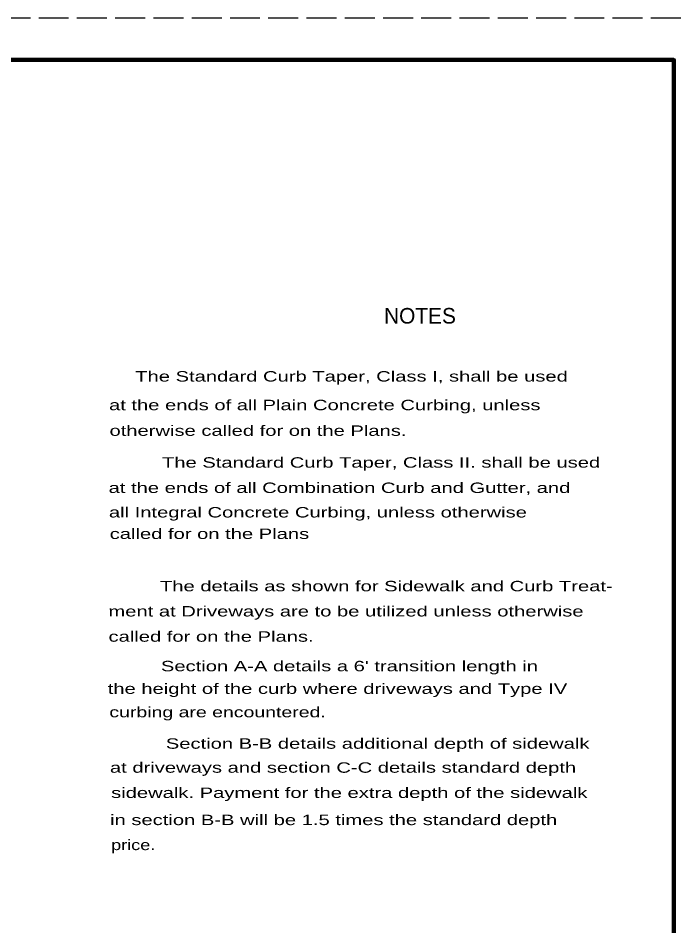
# Model space of a CAD drawing. Extents: x 75.6 to 110.9, y 28 to 50.
# Drawn here: x 102.83 to 110.8, y 39.07 to 49.98 of the extents above; entities that cross this region are included whole.
import ezdxf

# ---------------------------------------------------------------- set-up
doc = ezdxf.new("R2010")
doc.units = 0
doc.header["$LTSCALE"] = 0.06
doc.header["$PDMODE"] = 32
doc.header["$PDSIZE"] = 0.03
doc.linetypes.add('LONG_DASHED', pattern=[7.5, 6, -1.5])
doc.layers.add('1', color=7, linetype='Continuous', lineweight=25)
doc.layers.add('3', color=7, linetype='Continuous', lineweight=13)

msp = doc.modelspace()

# ---------------------------------------------------------------- linework, layer by layer
at = {"layer": '1', "linetype": 'LONG_DASHED'}
msp.add_line((110.8, 49.97992), (75.6, 49.97992), dxfattribs=at)
at = {"layer": '1', "lineweight": 158}
msp.add_line((110.71667, 49.47992), (78.21667, 49.47992), dxfattribs=at)
msp.add_lwpolyline([(110.71667, 49.47992), (110.71667, 28.47992), (78.21667, 28.47992)], dxfattribs=at)
at = {"layer": '1'}
msp.add_point((110.71667, 49.47992), dxfattribs=at)

# ---------------------------------------------------------------- texts
for s, width, p in [('The Standard Curb Taper, Class II. shall be used', 1.45, (104.56267, 44.57692)), ('at the ends of all Combination Curb and Gutter, and', 1.45, (103.92058, 44.27275)), ('all Integral Concrete Curbing, unless otherwise ', 1.45, (103.92417, 43.97825)), ('called for on the Plans', 1.45, (103.93383, 43.71992)), ('The details as shown for Sidewalk and Curb Treat-', 1.45, (104.53833, 43.09083)), ('ment at Driveways are to be utilized unless otherwise', 1.45, (103.91858, 42.78833)), ('called for on the Plans. ', 1.45, (103.91975, 42.48475)), ("Section A-A details a 6' transition length in", 1.45, (104.5495, 42.1295)), ('the height of the curb where driveways and Type IV', 1.45, (103.91025, 41.85792)), ('curbing are encountered.', 1.4, (103.92958, 41.57667)), ('Section B-B details additional depth of sidewalk', 1.45, (104.60858, 41.1985)), ('at driveways and section C-C details standard depth', 1.45, (103.93675, 40.91008)), ('sidewalk. Payment for the extra depth of the sidewalk', 1.45, (103.95092, 40.60692)), ('in section B-B will be 1.5 times the standard depth', 1.45, (103.93858, 40.28067)), ('price.', 1.3, (103.95083, 39.98008))]:
    msp.add_text(s, height=0.125, dxfattribs=dict(at, width=width)).set_placement(p)
at = {"layer": '3'}
msp.add_text('NOTES', height=0.1875, dxfattribs=at).set_placement((107.23208, 46.30858))
at = {"layer": '3', "width": 1.45}
for s, p in [('     The Standard Curb Taper, Class I, shall be used ', (103.90417, 45.612)), ('at the ends of all Plain Concrete Curbing, unless ', (103.9255, 45.26758)), ('otherwise called for on the Plans.', (103.93133, 44.95942))]:
    msp.add_text(s, height=0.125, dxfattribs=at).set_placement(p)

doc.saveas('drawing.dxf')
